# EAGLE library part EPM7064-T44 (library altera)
EPM7064 MAX 7000 family
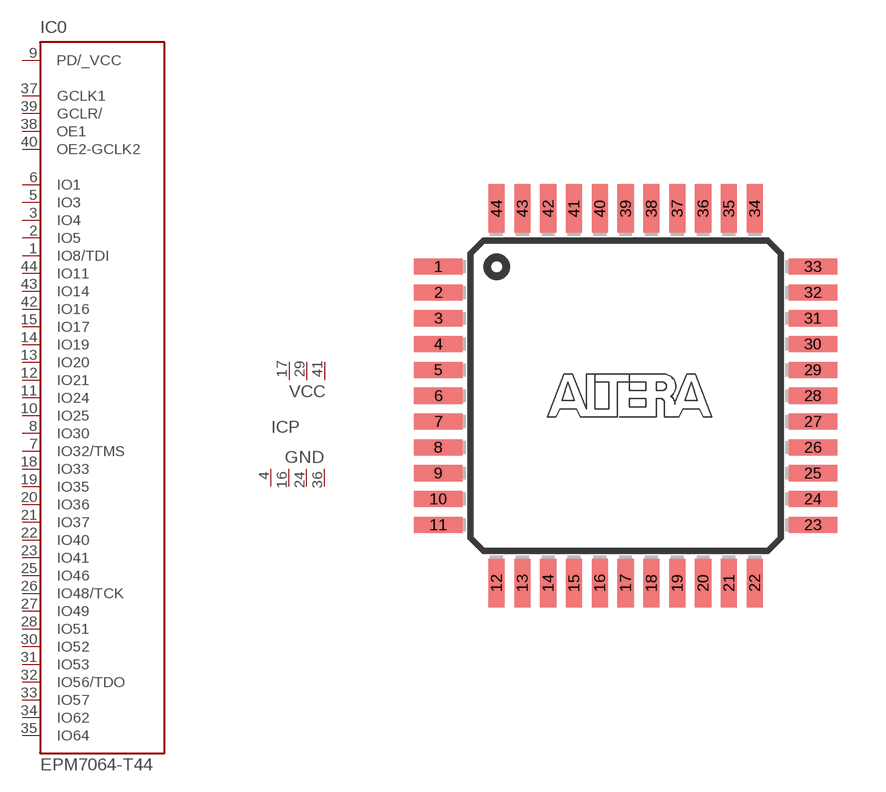
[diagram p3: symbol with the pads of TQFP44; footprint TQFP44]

Designator prefix IC; gates 0=7064-T44 P=PWR3-4

## EPM7064-T44  [TQFP44]
1  0:IO8/TDI
2  0:IO5
3  0:IO4
4  P:GND  pwr
5  0:IO3
6  0:IO1
7  0:IO32/TMS
8  0:IO30
9  0:PD/_VCC  pas
10  0:IO25
11  0:IO24
12  0:IO21
13  0:IO20
14  0:IO19
15  0:IO17
16  P:GND  pwr
17  P:VCC  pwr
18  0:IO33
19  0:IO35
20  0:IO36
21  0:IO37
22  0:IO40
23  0:IO41
24  P:GND  pwr
25  0:IO46
26  0:IO48/TCK
27  0:IO49
28  0:IO51
29  P:VCC  pwr
30  0:IO52
31  0:IO53
32  0:IO56/TDO
33  0:IO57
34  0:IO62
35  0:IO64
36  P:GND  pwr
37  0:GCLK1  in
38  0:OE1  in
39  0:GCLR/  in
40  0:OE2-GCLK2  in
41  P:VCC  pwr
42  0:IO16
43  0:IO14
44  0:IO11

## Footprint TQFP44 (pad centres in mm)
Plastic Thin Quad Flat Pack
smd 1.5 x 0.5: 1 -5.8,4; 2 -5.8,3.2; 3 -5.8,2.4; 4 -5.8,1.6; 5 -5.8,0.8; 6 -5.8,0; 7 -5.8,-0.8; 8 -5.8,-1.6; 9 -5.8,-2.4; 10 -5.8,-3.2; 11 -5.8,-4; 23 5.8,-4; 24 5.8,-3.2; 25 5.8,-2.4; 26 5.8,-1.6; 27 5.8,-0.8; 28 5.8,0; 29 5.8,0.8; 30 5.8,1.6; 31 5.8,2.4; 32 5.8,3.2; 33 5.8,4
smd 0.5 x 1.5: 12 -4,-5.8; 13 -3.2,-5.8; 14 -2.4,-5.8; 15 -1.6,-5.8; 16 -0.8,-5.8; 17 0,-5.8; 18 0.8,-5.8; 19 1.6,-5.8; 20 2.4,-5.8; 21 3.2,-5.8; 22 4,-5.8; 34 4,5.8; 35 3.2,5.8; 36 2.4,5.8; 37 1.6,5.8; 38 0.8,5.8; 39 0,5.8; 40 -0.8,5.8; 41 -1.6,5.8; 42 -2.4,5.8; 43 -3.2,5.8; 44 -4,5.8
